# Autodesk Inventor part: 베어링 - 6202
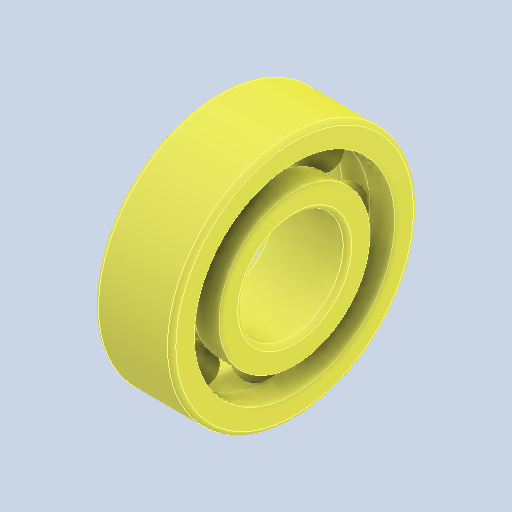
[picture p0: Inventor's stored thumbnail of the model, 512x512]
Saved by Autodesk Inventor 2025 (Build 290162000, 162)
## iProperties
Created: 2025-08
Part Number: 베어링 - 6202
Material: 강, 연강
Description: 깊은 그루브 볼 베어링
Document SubType Name: Modeling
Designer: infra028
Density: 7.86 g/cm^3
Appearance: 기본값
Author: jhkim
Sending System: Autodesk Inventor 2026
Preprocessor: ST-DEVELOPER v20.1
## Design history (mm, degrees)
feature "Solid1"
feature "Solid1:1"
feature "Solid1:2"
feature "Solid1:3"
feature "Solid1:4"
feature "Solid1:5"
feature "Solid1:6"
feature "Solid1:7"
feature "Solid1:8"
feature "Solid1:9"
node "솔리드1"
node "솔리드2"
node "솔리드3"
node "솔리드4"
node "솔리드5"
node "솔리드6"
node "솔리드7"
node "솔리드8"
node "솔리드9"
node "솔리드10"
